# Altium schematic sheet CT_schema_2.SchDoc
size 293 x 156 mm
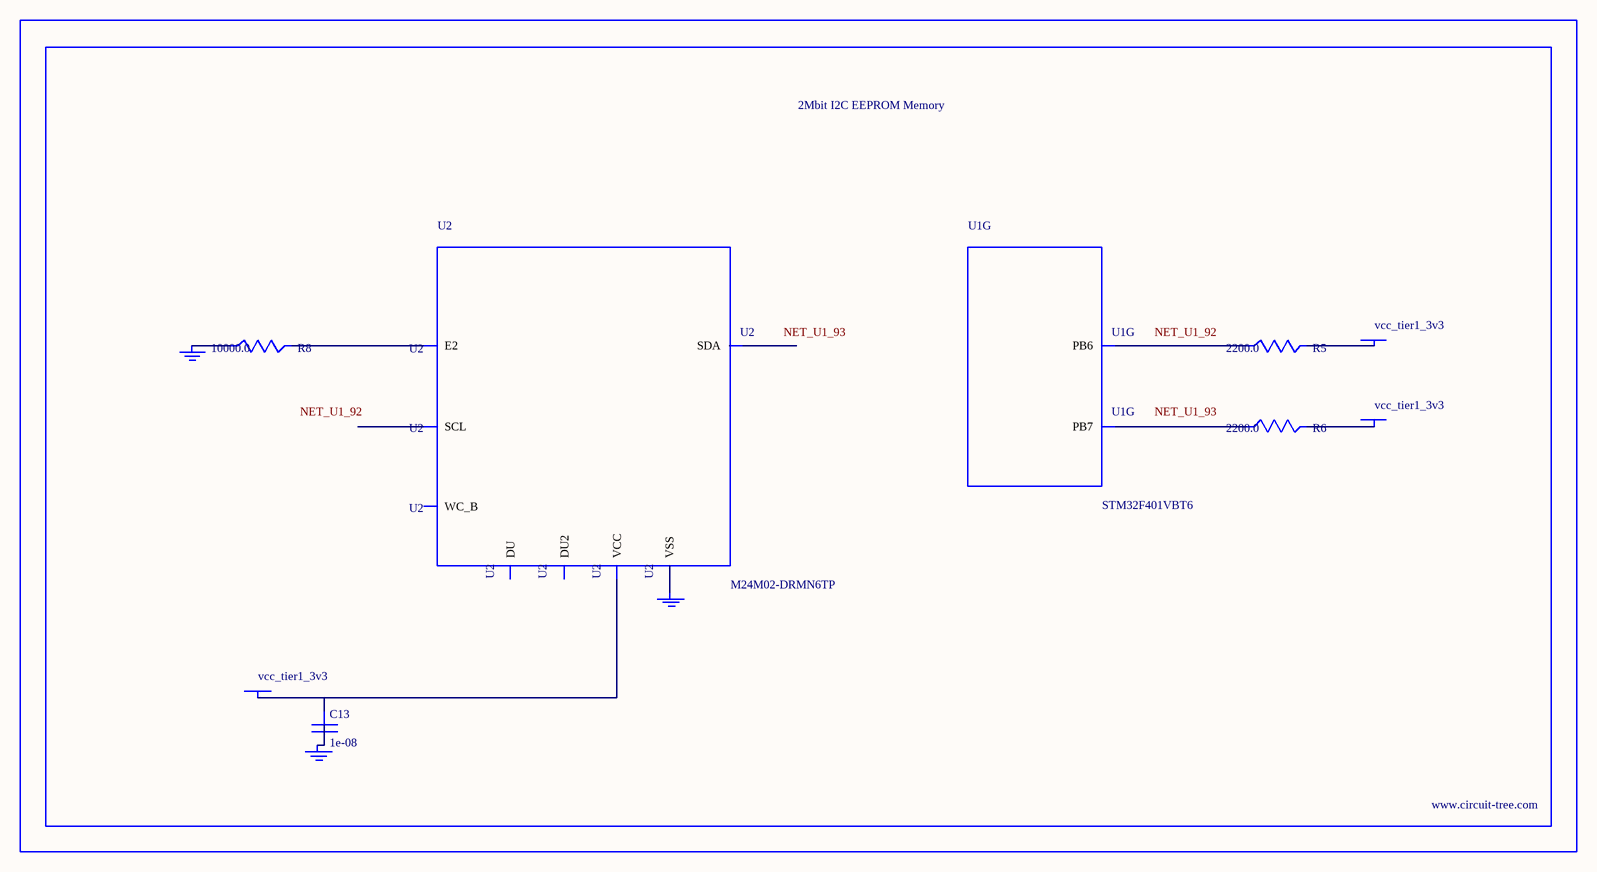
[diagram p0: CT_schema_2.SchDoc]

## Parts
BORDER1  (no value)
C13  1e-08  [C0402]
GND_INSTANCE_1_0  (no value)
GND_INSTANCE_1_1  (no value)
GND_INSTANCE_1_2  (no value)
POWER_INSTANCE_1_0  vcc_tier1_3v3
POWER_INSTANCE_1_1  vcc_tier1_3v3
POWER_INSTANCE_1_2  vcc_tier1_3v3
R5  2200.0  [R0603]
R6  2200.0  [R0603]
R8  10000.0  [R0603]
U1  STM32F401VBT6  [LQFP100]  (part G of 10)
U2  M24M02-DRMN6TP  [SOIC-8]

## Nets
NetC13_1: C13.1 POWER_INSTANCE_1_0.0(PWR) U2.8(VCC)
NetC13_2: C13.2 GND_INSTANCE_1_1.0(GND)
NetGND_INSTANCE_1_0_0: GND_INSTANCE_1_0.0(GND) R8.1
NetGND_INSTANCE_1_2_0: GND_INSTANCE_1_2.0(GND) U2.4(VSS)
NetPOWER_INSTANCE_1_1_0: POWER_INSTANCE_1_1.0(PWR) R5.2
NetPOWER_INSTANCE_1_2_0: POWER_INSTANCE_1_2.0(PWR) R6.2
NetR5_1: R5.1 U1.92(PB6)
NetR6_1: R6.1 U1.93(PB7)
NetR8_2: R8.2 U2.3(E2)

Not connected (* = marked no-connect by the designer): U2 1(DU) 2(DU2) 5(SDA) 6(SCL) 7(WC_B)

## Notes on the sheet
- Labels drawn without touching a wire or pin: NET_U1_92, NET_U1_93

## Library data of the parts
BORDER1 = BORDER_PAGE1
C13 = C0402C103K3RAC
GND_INSTANCE_1_0-GND_INSTANCE_1_2 = GND
POWER_INSTANCE_1_0-POWER_INSTANCE_1_2 = PWR
R5 R6 = RC0603JR-072K2L
R8 = RC0603JR-0710KL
